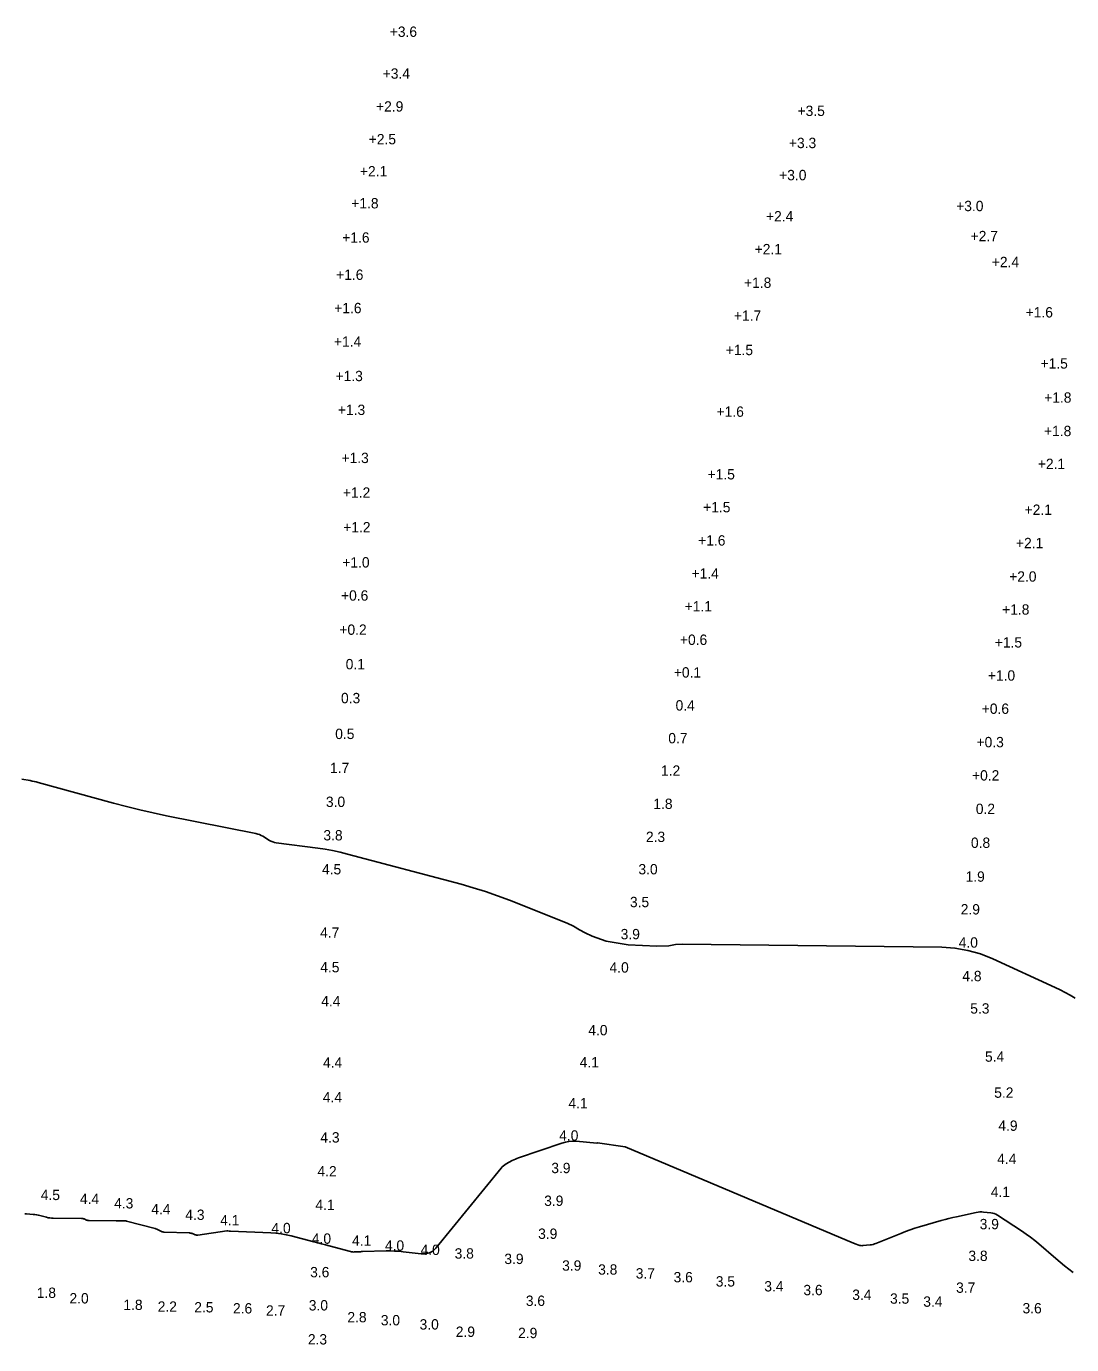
# Model space of a CAD drawing. Extents: x 837127 to 848654, y 3074248 to 3079868.
# Drawn here: x 844836.9 to 845153, y 3079089.9 to 3079488.4 of the extents above; entities that cross this region are included whole.
import ezdxf

# ---------------------------------------------------------------- set-up
doc = ezdxf.new("R2010")
doc.units = 0
doc.layers.add('V-HYDS-MAJR', color=7, linetype='Continuous')
doc.layers.add('V-HYDS-SOUN', color=7, linetype='Continuous')

msp = doc.modelspace()

# ---------------------------------------------------------------- linework, layer by layer
at = {"layer": 'V-HYDS-MAJR'}
msp.add_line((845012.23, 3079211.91), (845018.91, 3079210.83), dxfattribs=at)
for points in [[(844835.53, 3079260.86), (844838.08, 3079260.42), (844838.69, 3079260.3), (844839.3, 3079260.18), (844839.9, 3079260.03), (844840.5, 3079259.88), (844863.23, 3079253.62), (844867.22, 3079252.55), (844871.24, 3079251.56), (844875.27, 3079250.65), (844879.31, 3079249.8), (844906.35, 3079244.42), (844906.9, 3079244.28), (844907.43, 3079244.1), (844907.95, 3079243.87), (844908.44, 3079243.59), (844910.39, 3079242.36), (844910.88, 3079242.09), (844911.4, 3079241.87), (844911.94, 3079241.71), (844912.5, 3079241.61), (844925.01, 3079239.99), (844927.28, 3079239.66), (844929.53, 3079239.26), (844931.77, 3079238.78), (844933.99, 3079238.23), (844968.36, 3079229.1), (844972.07, 3079228.05), (844975.75, 3079226.9), (844979.39, 3079225.64), (844982.99, 3079224.27), (845000.4, 3079217.36), (845002.38, 3079216.44), (845004.22, 3079215.3), (845005.9, 3079214.41), (845007.97, 3079213.37), (845012.23, 3079211.91)], [(845018.91, 3079210.83), (845027.56, 3079210.35), (845031.2, 3079210.5), (845033.24, 3079210.89), (845035.35, 3079211), (845113.71, 3079210.03), (845117.7, 3079209.78), (845121.6, 3079209.11), (845125.4, 3079208.04), (845129.12, 3079206.56), (845147.98, 3079197.91), (845149.54, 3079197.17), (845151.08, 3079196.39), (845152.6, 3079195.56), (845154.1, 3079194.7)], [(845017.97, 3079149.76), (845009.64, 3079150.88), (845009.42, 3079150.87), (845003.2, 3079151.4), (845002.09, 3079151.44), (845001, 3079151.36), (844999.92, 3079151.17), (844998.85, 3079150.86), (844985.75, 3079146.37), (844985.27, 3079146.2), (844984.79, 3079146), (844984.32, 3079145.78), (844983.86, 3079145.55), (844982.04, 3079144.57), (844981.6, 3079144.3), (844981.19, 3079144), (844980.82, 3079143.65), (844980.48, 3079143.27), (844960.77, 3079119.12), (844959.85, 3079118.22), (844958.81, 3079117.63), (844957.64, 3079117.33), (844956.35, 3079117.34), (844950.84, 3079118.01), (844949.55, 3079118.14), (844948.27, 3079118.22), (844946.98, 3079118.26), (844945.68, 3079118.25), (844938.52, 3079118.04), (844938.23, 3079118.03), (844937.93, 3079118.02), (844937.63, 3079118), (844937.33, 3079117.99), (844936.14, 3079117.93), (844935.84, 3079117.92), (844935.54, 3079117.94), (844935.25, 3079117.99), (844934.96, 3079118.05), (844928.52, 3079119.79), (844927.35, 3079120.1), (844926.18, 3079120.41), (844925.01, 3079120.72), (844923.83, 3079121.03), (844917.02, 3079122.81), (844915.48, 3079123.16), (844913.94, 3079123.43), (844912.38, 3079123.62), (844910.81, 3079123.72), (844898.63, 3079124.19), (844898.53, 3079124.19), (844898.44, 3079124.2), (844898.34, 3079124.21), (844898.25, 3079124.23), (844897.88, 3079124.29), (844897.78, 3079124.31), (844897.69, 3079124.31), (844897.6, 3079124.31), (844897.5, 3079124.3), (844888.81, 3079123.03), (844888.59, 3079123.02), (844888.37, 3079123.03), (844888.16, 3079123.07), (844887.95, 3079123.14), (844887.13, 3079123.49), (844886.92, 3079123.57), (844886.71, 3079123.62), (844886.49, 3079123.66), (844886.27, 3079123.68), (844878.45, 3079123.96), (844878.22, 3079123.99), (844877.99, 3079124.03), (844877.78, 3079124.11), (844877.57, 3079124.21), (844876.74, 3079124.66), (844876.54, 3079124.77), (844876.32, 3079124.86), (844876.1, 3079124.94), (844875.88, 3079125.01), (844867.24, 3079127.27), (844866.98, 3079127.32), (844866.72, 3079127.36), (844866.46, 3079127.38), (844866.2, 3079127.38), (844865.15, 3079127.35), (844864.89, 3079127.34), (844864.63, 3079127.34), (844864.37, 3079127.34), (844864.1, 3079127.34), (844855.92, 3079127.42), (844855.72, 3079127.44), (844855.52, 3079127.47), (844855.33, 3079127.52), (844855.14, 3079127.59), (844854.4, 3079127.91), (844854.22, 3079127.98), (844854.03, 3079128.03), (844853.83, 3079128.06), (844853.63, 3079128.08), (844845.03, 3079128.14), (844844.52, 3079128.16), (844844, 3079128.21), (844843.5, 3079128.3), (844843, 3079128.41), (844840.97, 3079128.96), (844840.49, 3079129.08), (844839.99, 3079129.18), (844839.5, 3079129.25), (844839, 3079129.29), (844837, 3079129.43), (844836.5, 3079129.47)], [(845153.47, 3079111.72), (845152.14, 3079112.74), (845150.83, 3079113.79), (845149.54, 3079114.85), (845148.26, 3079115.93), (845143.11, 3079120.35), (845141.85, 3079121.39), (845140.56, 3079122.4), (845139.24, 3079123.36), (845137.88, 3079124.28), (845130.59, 3079129.07), (845130.11, 3079129.34), (845129.62, 3079129.55), (845129.1, 3079129.7), (845128.56, 3079129.79), (845126.35, 3079130), (845125.8, 3079130.03), (845125.25, 3079130.02), (845124.71, 3079129.97), (845124.16, 3079129.88), (845118.23, 3079128.6), (845117.06, 3079128.34), (845115.9, 3079128.06), (845114.74, 3079127.76), (845113.59, 3079127.44), (845107.01, 3079125.54), (845105.57, 3079125.1), (845104.15, 3079124.63), (845102.73, 3079124.12), (845101.33, 3079123.57), (845093.82, 3079120.51), (845093.39, 3079120.35), (845092.94, 3079120.22), (845092.49, 3079120.13), (845092.03, 3079120.07), (845089.83, 3079119.85), (845089.54, 3079119.83), (845089.25, 3079119.85), (845088.97, 3079119.9), (845088.69, 3079119.98), (845087.58, 3079120.36), (845087.31, 3079120.48), (845087.08, 3079120.63), (845017.97, 3079149.76)]]:
    msp.add_lwpolyline(points, dxfattribs=at)

# ---------------------------------------------------------------- texts
at = {"layer": 'V-HYDS-SOUN'}
for s, p in [('+3.6 ', (844946.81, 3079485.25)), ('+3.4 ', (844944.67, 3079472.6)), ('+2.9 ', (844942.66, 3079462.66)), ('+3.5 ', (845070.12, 3079461.33)), ('+2.5 ', (844940.45, 3079452.76)), ('+3.3 ', (845067.51, 3079451.61)), ('+2.1 ', (844937.78, 3079443.06)), ('+3.0 ', (845064.55, 3079441.91)), ('+1.8 ', (844935.17, 3079433.39)), ('+3.0 ', (845118.08, 3079432.56)), ('+2.4 ', (845060.58, 3079429.45)), ('+1.6 ', (844932.44, 3079423.03)), ('+2.7 ', (845122.45, 3079423.47)), ('+2.1 ', (845057.15, 3079419.52)), ('+2.4 ', (845128.85, 3079415.63)), ('+1.6 ', (844930.59, 3079411.79)), ('+1.8 ', (845053.94, 3079409.37)), ('+1.6 ', (844930.01, 3079401.71)), ('+1.7 ', (845050.87, 3079399.41)), ('+1.6 ', (845139.09, 3079400.42)), ('+1.4 ', (844929.93, 3079391.57)), ('+1.5 ', (845048.42, 3079389.03)), ('+1.5 ', (845143.59, 3079384.97)), ('+1.3 ', (844930.41, 3079381.17)), ('+1.8 ', (845144.69, 3079374.66)), ('+1.3 ', (844931.12, 3079370.95)), ('+1.6 ', (845045.63, 3079370.4)), ('+1.8 ', (845144.65, 3079364.55)), ('+1.3 ', (844932.21, 3079356.41)), ('+2.1 ', (845142.78, 3079354.61)), ('+1.5 ', (845042.92, 3079351.46)), ('+1.2 ', (844932.65, 3079345.93)), ('+1.5 ', (845041.57, 3079341.52)), ('+2.1 ', (845138.78, 3079340.75)), ('+1.2 ', (844932.73, 3079335.46)), ('+1.6 ', (845040.06, 3079331.47)), ('+2.1 ', (845136.16, 3079330.68)), ('+1.0 ', (844932.46, 3079324.84)), ('+1.4 ', (845038.07, 3079321.49)), ('+2.0 ', (845134.12, 3079320.56)), ('+0.6 ', (844932.07, 3079314.82)), ('+1.1 ', (845035.99, 3079311.55)), ('+1.8 ', (845131.98, 3079310.59)), ('+0.2 ', (844931.57, 3079304.5)), ('+0.6 ', (845034.55, 3079301.45)), ('+1.5 ', (845129.76, 3079300.65)), ('0.1', (844933.48, 3079294.07)), ('+0.1 ', (845032.71, 3079291.57)), ('+1.0 ', (845127.66, 3079290.64)), ('0.3', (844932.06, 3079283.81)), ('0.4', (845033.24, 3079281.6)), ('+0.6 ', (845125.82, 3079280.59)), ('0.5', (844930.31, 3079272.99)), ('0.7', (845031.03, 3079271.7)), ('+0.3 ', (845124.24, 3079270.5)), ('1.7', (844928.74, 3079262.7)), ('1.2', (845028.82, 3079261.89)), ('+0.2 ', (845122.88, 3079260.44)), ('3.0', (844927.5, 3079252.46)), ('1.8', (845026.51, 3079251.85)), ('0.2', (845124.02, 3079250.32)), ('3.8', (844926.74, 3079242.34)), ('2.3', (845024.27, 3079241.87)), ('0.8', (845122.55, 3079240.08)), ('4.5', (844926.31, 3079232.07)), ('3.0', (845022, 3079232.08)), ('1.9', (845120.92, 3079229.86)), ('3.5', (845019.43, 3079222.16)), ('2.9', (845119.46, 3079219.96)), ('4.7', (844925.75, 3079212.92)), ('3.9', (845016.63, 3079212.46)), ('4.0', (845118.85, 3079209.93)), ('4.5', (844925.78, 3079202.47)), ('4.0', (845013.26, 3079202.39)), ('4.8', (845119.94, 3079199.79)), ('4.4', (844926.08, 3079192.2)), ('5.3', (845122.34, 3079189.99)), ('4.0', (845006.84, 3079183.43)), ('5.4', (845126.8, 3079175.44)), ('4.4', (844926.62, 3079173.64)), ('4.1', (845004.22, 3079173.71)), ('4.4', (844926.57, 3079163.15)), ('5.2', (845129.59, 3079164.54)), ('4.1', (845000.83, 3079161.35)), ('4.3', (844925.82, 3079151.02)), ('4.0', (844998.04, 3079151.59)), ('4.9', (845130.83, 3079154.56)), ('4.4', (845130.49, 3079144.54)), ('4.2', (844924.94, 3079140.77)), ('3.9', (844995.65, 3079141.76)), ('4.5', (844841.27, 3079133.62)), ('4.4', (844853.11, 3079132.44)), ('4.3', (844863.46, 3079131.08)), ('3.9', (844993.5, 3079131.86)), ('4.1', (845128.56, 3079134.55)), ('4.4', (844874.7, 3079129.34)), ('4.3', (844884.98, 3079127.63)), ('4.1', (844924.31, 3079130.61)), ('4.1', (844895.53, 3079125.97)), ('4.0', (844911.03, 3079123.6)), ('3.9', (845125.19, 3079124.81)), ('4.0', (844923.25, 3079120.42)), ('4.1', (844935.38, 3079119.8)), ('3.9', (844991.67, 3079121.9)), ('4.0', (844945.34, 3079118.32)), ('4.0', (844956.12, 3079117.02)), ('3.8', (844966.42, 3079115.93)), ('3.8', (845121.78, 3079115.22)), ('3.9', (844981.45, 3079114.29)), ('3.9', (844998.93, 3079112.28)), ('3.6', (844922.73, 3079110.28)), ('3.8', (845009.82, 3079111.08)), ('3.7', (845021.19, 3079109.91)), ('3.6', (845032.64, 3079108.76)), ('3.5', (845045.39, 3079107.49)), ('1.8', (844840.07, 3079104.05)), ('3.4', (845060.06, 3079106)), ('3.6', (845071.89, 3079104.87)), ('3.4', (845086.66, 3079103.45)), ('3.7', (845118.06, 3079105.59)), ('2.0', (844849.95, 3079102.37)), ('1.8', (844866.26, 3079100.4)), ('2.2', (844876.63, 3079099.87)), ('2.5', (844887.69, 3079099.66)), ('2.6', (844899.39, 3079099.34)), ('3.0', (844922.32, 3079100.25)), ('3.6', (844987.95, 3079101.63)), ('3.5', (845098.09, 3079102.29)), ('3.4', (845108.13, 3079101.37)), ('3.6', (845138.15, 3079099.37)), ('2.7', (844909.38, 3079098.68)), ('2.8', (844933.99, 3079096.67)), ('3.0', (844944.1, 3079095.75)), ('3.0', (844955.82, 3079094.49)), ('2.9', (844966.77, 3079092.27)), ('2.9', (844985.62, 3079091.89)), ('2.3', (844922.04, 3079089.97))]:
    msp.add_text(s, height=3.125, dxfattribs=at).set_placement(p)

doc.saveas('drawing.dxf')
